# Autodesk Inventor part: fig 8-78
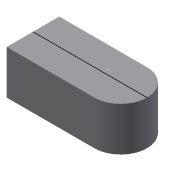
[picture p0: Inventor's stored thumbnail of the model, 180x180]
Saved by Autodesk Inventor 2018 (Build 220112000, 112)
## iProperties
Created: 2011-07
Part Number: fig 8-78
Material: Generic
Document SubType Name: Modeling
Designer: CadCim
Density: 1 g/cm^3
Appearance: Default
Author: CadCim
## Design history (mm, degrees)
sketch "Sketch1"
  geometry: L1 (-16, 5)-(-16, -7); L2 (-16, -7)-(4, -7); L3 (4, 5)-(-16, 5); A1 r 6 centre (4, -1) between (4, -7) and (4, 5); 1 further point
  constraints: 6 end point, 2 point on circle, 2 tangent, 1 centre point, 1 parallel, 1 perpendicular, 1 vertical
extrude "Extrusion1" new body sketch "Sketch1" distance "d0" = 10; taper "d1" = 0 deg
sketch "Sketch2"
  geometry: L1 (-16, -1)-(10, -1); 1 further point
  constraints: 2 end point, 1 horizontal
body "Solid1"
